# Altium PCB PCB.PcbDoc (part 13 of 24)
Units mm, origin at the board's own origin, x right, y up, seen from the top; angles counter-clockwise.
Board outline 100 x 160 mm, 10 copper layers (TOP_L1, L2, L3, L4, L5, L6, L7, L8, L9, BOTTOM_L10), stack 1.946 mm thick; 1358 components, 1149 nets, 6777 pads, 10914 vias.
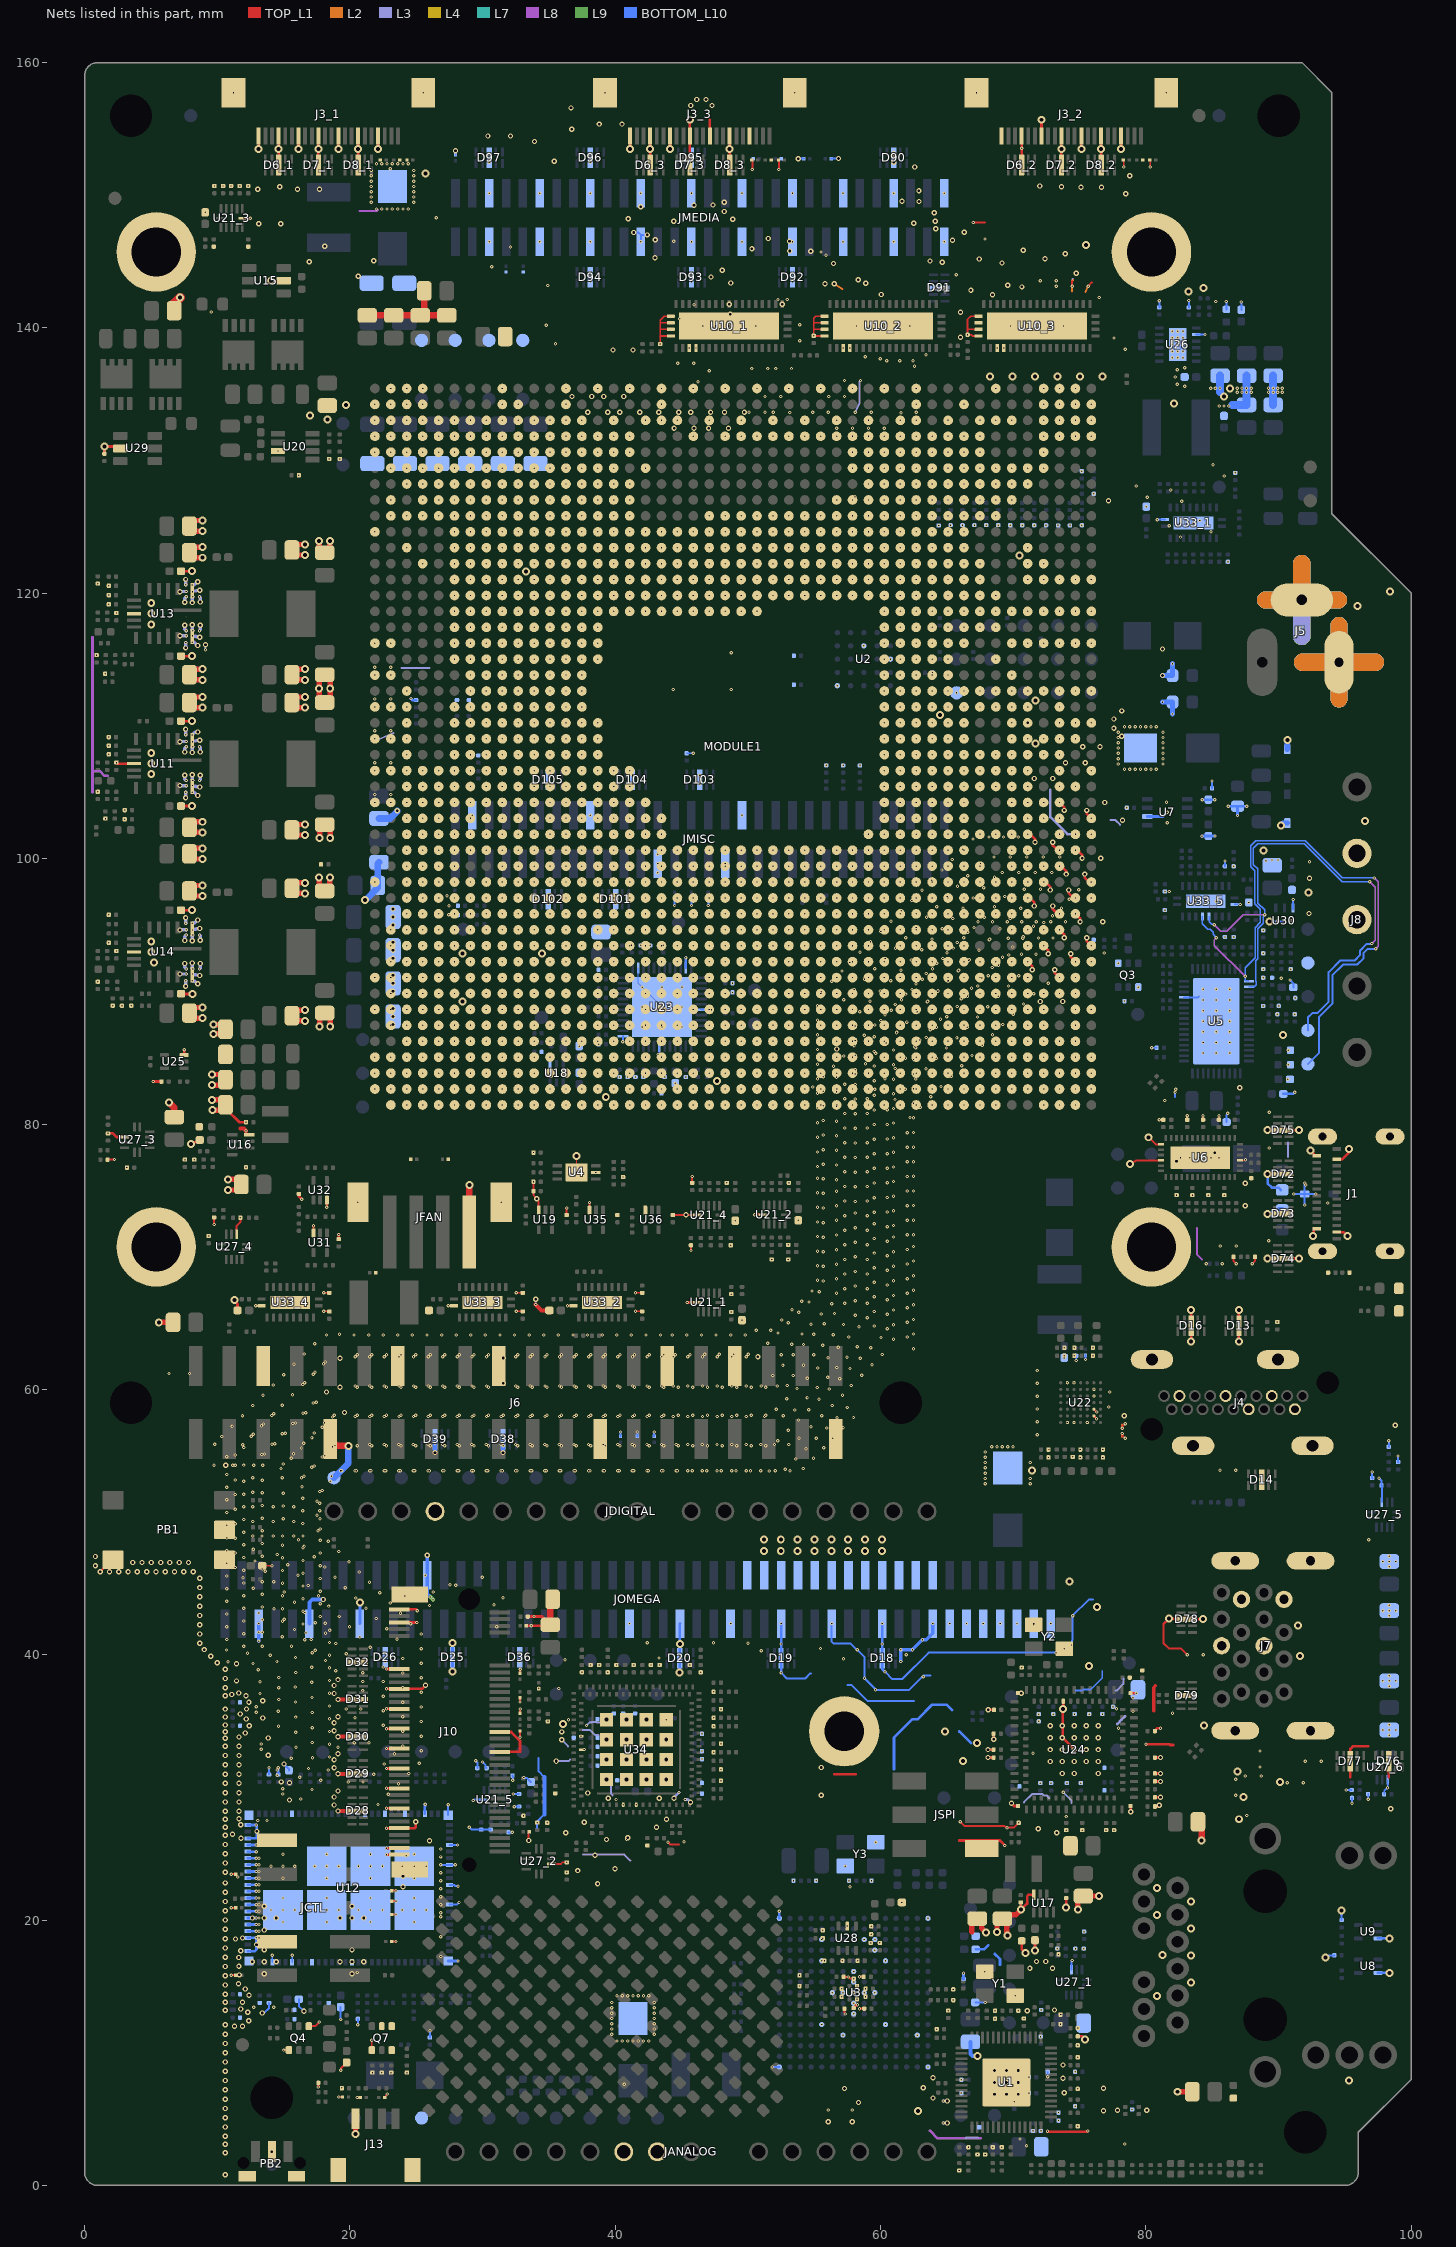
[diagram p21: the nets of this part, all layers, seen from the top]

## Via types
v1: diameter 0.25, hole 0.1, TOP_L1 to L2, tented both sides, 3439 vias
v2: diameter 0.25, hole 0.1, L2 to L3, tented both sides, 2256 vias
v3: diameter 0.25, hole 0.1, L9 to BOTTOM_L10, tented both sides, 1685 vias
v4: diameter 0.25, hole 0.1, L8 to L9, tented both sides, 1675 vias
v5: diameter 0.4, hole 0.2, L3 to L8, tented both sides, 1251 vias
v6: diameter 0.6, hole 0.3, TOP_L1 to BOTTOM_L10, tented both sides, 600 vias
v7: diameter 0.24, hole 0.1, TOP_L1 to L2, tented both sides, 8 vias

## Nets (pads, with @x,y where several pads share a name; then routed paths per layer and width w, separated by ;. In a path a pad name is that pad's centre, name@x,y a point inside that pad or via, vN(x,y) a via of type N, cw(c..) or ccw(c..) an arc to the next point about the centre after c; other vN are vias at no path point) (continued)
GND: (continued)
  other v2: 10.6,0.8 10.6,2.452 14.117,2.549 71,3 10.6,3.102 78.406,3.118 70.5,3.5 10.6,3.702 10.6,4.402 10.6,5.102 76.798,5.62 77.848,5.674 80.048,5.674 10.6,5.802 10.6,6.502 68.581,6.859 69.481,6.859 70.381,6.859 73.848,6.974 10.6,7.202 76.798,7.32 68.581,7.759 69.481,7.759 70.381,7.759 10.6,7.902 73.748,8.074 10.6,8.602 68.581,8.659 69.481,8.659 70.381,8.659 73.748,9.074 10.6,9.302 10.6,10.002 10.6,10.702 10.6,11.402 11.3,12 11.9,12 10.6,12.102 12.367,12.413 12.293,13.052 71.048,13.174 10.6,13.2 73.1,13.225 11.762,13.3 10.6,13.8 11.901,13.801 12.397,14.327 10.6,14.4 12.1,14.8 10.6,15.1 11.6,15.2 10.6,15.8 11.657,15.866 71.25,16.375 72.95,16.375 10.6,16.5 11.632,16.525 71.75,16.875 72.45,16.875 11.628,17.175 10.6,17.2 11.776,17.689 10.6,17.9 11.373,18.578 10.6,18.6 11.902,18.65 10.6,19.3 10.6,20 10.6,20.7 10.6,21.4 10.6,22.1 38.665,22.744 10.6,22.8 10.6,23.601 37.179,23.729 39.975,23.875 10.6,24.301 38.465,24.889 10.6,25.001 69.36,25.622 10.6,25.701 45.173,25.913 26,25.98 39.341,26.074 11.789,26.167 40.94,26.203 10.6,26.401 11.144,26.459 36.275,26.575 73.269,26.575 71.875,26.875 10.6,27.001 43.103,26.997 11.777,27.176 37.67,27.373 24.961,27.403 10.6,27.6 43.856,27.609 11.64,27.634 73.991,27.799 87.6,27.875 78.841,28.174 10.6,28.201 11.64,28.201 81.009,28.643 18.806,28.675 10.6,28.901 11.64,28.901 15.443,29.052 40.06,29.081 16.287,29.12 39.46,29.181 43.302,29.175 81.091,29.249 18.806,29.275 55.52,29.403 86.766,29.408 14.943,29.502 37.924,29.573 10.6,29.601 11.64,29.601 73.766,29.639 19.106,29.725 17.141,29.844 14.943,29.902 10.6,30.301 11.64,30.301 15.443,30.352 90.64,30.349 91.84,30.349 14.825,30.413 17.788,30.527 86.766,30.608 16.223,30.762 87.482,30.86 88.682,30.86 14.525,30.913 10.6,31.001 11.64,31.001 19.106,31.025 73.691,31.049 74.591,31.049 76.391,31.049 14.525,31.313 18.377,31.316 16.876,31.422 18.806,31.475 55.52,31.503 88.597,31.542 10.6,31.701 11.64,31.701 15.025,31.763 72.791,31.949 73.691,31.949 74.591,31.949 75.491,31.949 76.391,31.949 92,31.975 93.2,31.975 18.806,32.075 15.586,32.184 17.176,32.246 68.091,32.249 81.091,32.249 18.462,32.294 10.6,32.401 11.64,32.401 13.849,32.425 19.106,32.525 88.597,32.742 68.091,32.849 72.791,32.849 73.691,32.849 74.591,32.849 75.491,32.849 76.391,32.849 13.327,32.875 15.931,33.026 10.6,33.101 11.64,33.101 18.462,33.251 13.327,33.275 17.164,33.382 68.516,33.624 10.6,33.701 13.849,33.725 72.791,33.749 73.691,33.749 74.591,33.749 75.491,33.749 76.391,33.749 11.64,33.801 19.106,33.825 12.1,34.101 15.918,34.162 10.6,34.201 18.462,34.207 18.806,34.275 77.921,34.449 81.09,34.453 17.168,34.507 14.609,34.612 12.417,34.651 72.791,34.649 73.691,34.649 74.591,34.649 75.491,34.649 76.391,34.649 37.832,34.67 10.6,34.701 18.806,34.875 36.471,35.099 12.185,35.149 18.46,35.183 13.427,35.225 10.6,35.301 15.906,35.298 19.106,35.325 11.733,35.535 81.994,35.58 17.156,35.643 12.927,35.675 14.597,35.748 79.021,35.749 68.116,35.849 10.6,35.901 12.202,35.909 77.778,35.926 12.927,36.075 18.46,36.139 12.386,36.422 15.893,36.435 13.427,36.525 14.64,36.625 19.106,36.625 79.021,36.749 17.143,36.779 10.6,36.901 12.165,36.901 11.097,37.004 13.226,37.075 18.46,37.096 18.806,37.075 70.605,37.085 11.613,37.11 10.6,37.501 14.64,37.505 15.881,37.571 18.806,37.675 25.7,37.7 17.131,37.915 13.226,37.955 11.45,38.024 18.46,38.052 19.106,38.125 10.6,38.201 14.64,38.287 15.915,38.655 13.099,38.871 10.6,38.901 18.46,39.008 17.118,39.051 11.45,39.324 12.7,39.341 10.005,39.396 10.806,39.459 14.496,39.495 15.903,39.791 9.51,39.891 13.991,39.949 18.46,39.965 84.304,40.004 12.282,40.102 17.153,40.136 10.691,40.349 9.015,40.386 12.003,40.629 13.391,40.649 15.591,40.649 8.674,40.859 18.46,40.921 10.719,41.151 17.091,41.149 14.891,41.349 8.674,41.559 12.003,41.585 16.691,41.649 13.397,41.681 18.475,41.838 10.719,42.108 8.674,42.259 16.469,42.313 18.131,42.379 14.923,42.519 12.003,42.542 13.397,42.637 17.76,42.878 8.674,42.959 10.719,43.064 16.469,43.27 14.923,43.476 12.003,43.498 13.397,43.594 8.674,43.659 17.76,43.834 10.719,44.021 16.469,44.226 8.674,44.359 14.923,44.432 12.003,44.454 13.397,44.55 17.76,44.79 10.719,44.977 8.674,45.059 16.469,45.182 14.923,45.388 12.003,45.411 13.397,45.507 17.76,45.747 8.674,45.759 10.719,45.933 16.469,46.139 1.179,46.254 1.879,46.254 2.579,46.254 3.279,46.254 3.979,46.254 4.679,46.254 5.379,46.254 6.079,46.254 6.779,46.254 7.479,46.254 8.179,46.254 12.003,46.367 14.923,46.345 13.397,46.463 0.817,46.7 17.76,46.703 10.719,46.89 3.629,46.954 4.329,46.954 5.029,46.954 5.729,46.954 6.429,46.954 7.129,46.954 7.829,46.954 16.469,47.095 14.923,47.301 12.003,47.324 0.817,47.4 13.397,47.419 17.76,47.66 10.719,47.846 16.469,48.052 14.923,48.258 12.003,48.28 13.397,48.376 17.76,48.616 10.719,48.803 13.377,48.946 14.923,48.946 16.466,48.946 12.003,49.236 13.397,49.332 17.76,49.478 10.719,49.759 16.446,49.889 12.003,50.193 14.966,50.246 17.745,50.257 13.397,50.289 10.719,50.716 16.446,50.845 17.733,50.851 12.003,51.149 14.966,51.202 13.397,51.245 17.732,51.426 10.719,51.672 16.446,51.802 12.003,52.106 14.966,52.159 13.397,52.201 17.728,52.302 10.719,52.628 16.391,52.649 12.003,53.062 18.505,53.08 13.397,53.158 14.891,53.349 16.351,53.348 10.719,53.585 19.283,53.858 20.383,53.858 21.483,53.858 22.583,53.858 23.683,53.858 24.783,53.858 25.883,53.858 26.983,53.858 28.083,53.858 29.183,53.858 30.283,53.858 31.383,53.858 32.483,53.858 33.583,53.858 34.683,53.858 35.783,53.858 36.883,53.858 37.983,53.858 39.083,53.858 40.183,53.858 41.283,53.858 42.383,53.858 43.483,53.858 44.583,53.858 45.459,53.858 46.559,53.858 47.666,53.858 48.766,53.858 49.866,53.858 50.966,53.858 52.05,53.858 53.162,53.858 85.575,53.9 86.775,53.9 54.159,54.035 17.129,54.126 10.65,54.269 12.003,54.292 13.44,54.269 14.974,54.371 54.937,54.813 10.719,54.91 17.906,54.904 13.346,55.089 15.752,55.149 55.715,55.591 12.003,55.622 18.684,55.682 9.819,55.867 14.124,55.867 21.483,55.849 22.583,55.849 23.683,55.849 24.783,55.849 25.883,55.849 26.983,55.849 28.083,55.849 29.183,55.849 30.283,55.849 31.383,55.849 32.483,55.849 33.583,55.849 34.683,55.849 35.783,55.849 36.883,55.849 37.983,55.849 39.083,55.849 40.183,55.849 41.283,55.849 42.383,55.849 43.483,55.849 44.583,55.849 45.459,55.849 46.559,55.849 47.666,55.849 48.766,55.849 49.866,55.849 50.966,55.849 51.998,55.849 53.072,55.849 16.53,55.927 53.852,56.32 56.392,56.32 78.424,56.319 10.34,56.445 12.559,56.474 71.8,56.586 14.901,56.645 17.308,56.705 57.169,57.098 54.75,57.175 11.118,57.223 13.337,57.251 78.424,57.409 15.679,57.422 18.085,57.482 71.8,57.552 57.947,57.876 51.25,57.95 20.397,57.958 21.497,57.958 22.597,57.958 23.697,57.958 24.797,57.958 25.897,57.958 26.997,57.958 28.097,57.958 29.197,57.958 30.297,57.958 31.397,57.958 32.497,57.958 33.597,57.958 34.697,57.958 35.797,57.958 36.897,57.958 37.997,57.958 39.097,57.958 40.197,57.958 41.297,57.958 42.397,57.958 43.497,57.958 44.372,57.958 45.472,57.958 46.579,57.958 47.679,57.958 48.779,57.958 49.879,57.958 11.896,58 52.657,58.01 55.563,58.01 78.357,58.019 14.115,58.029 18.809,58.048 16.457,58.2 19.596,58.25 53.52,58.45 71.8,58.517 77.199,58.671 12.673,58.778 56.341,58.788 14.893,58.807 17.235,58.978 54.456,59.365 71.8,59.483 13.451,59.556 57.119,59.566 15.671,59.585 18.23,59.796 77.275,59.8 19.25,60.15 55.234,60.143 20.397,60.258 21.497,60.258 22.597,60.258 23.697,60.258 24.797,60.258 25.897,60.258 26.997,60.258 28.097,60.258 29.197,60.258 30.297,60.258 32.497,60.258 33.597,60.258 34.697,60.258 35.797,60.258 36.897,60.258 37.997,60.258 39.097,60.258 40.197,60.258 41.297,60.258 42.397,60.258 43.497,60.258 44.372,60.258 45.472,60.258 46.579,60.258 47.679,60.258 48.779,60.258 49.879,60.258 51.012,60.258 52.197,60.258 52.949,60.296 57.796,60.296 14.229,60.334 16.449,60.363 71.8,60.449 56.012,60.921 53.406,61.047 58.574,61.074 15.007,61.112 17.226,61.141 71.8,61.414 56.688,61.65 54.184,61.825 59.351,61.851 15.785,61.89 18.004,61.918 19.25,62.35 31.557,62.365 57.466,62.428 20.397,62.458 21.497,62.458 22.597,62.458 23.697,62.458 24.797,62.458 25.897,62.458 26.997,62.458 28.097,62.458 29.197,62.458 30.297,62.458 32.497,62.458 33.597,62.458 34.697,62.458 35.797,62.458 36.897,62.458 37.997,62.458 39.097,62.458 40.197,62.458 41.297,62.458 42.397,62.458 43.497,62.458 44.372,62.458 45.472,62.458 46.579,62.458 47.679,62.458 48.779,62.458 49.879,62.458 50.75,62.45 52.518,62.618 54.962,62.603 60.129,62.629 16.563,62.667 62.476,63.069 58.244,63.206 55.638,63.333 53.296,63.396 17.34,63.445 60.972,63.78 18.233,64.101 20.308,64.099 21.408,64.099 22.508,64.099 23.608,64.099 24.708,64.099 25.808,64.099 26.908,64.099 28.008,64.099 29.108,64.099 30.208,64.099 31.308,64.099 32.408,64.099 33.508,64.099 34.608,64.099 35.708,64.099 36.808,64.099 37.908,64.099 39.008,64.099 40.108,64.099 41.208,64.099 42.308,64.099 43.408,64.099 44.284,64.099 45.384,64.099 46.491,64.099 47.591,64.099 48.691,64.099 49.791,64.099 56.416,64.111 19.22,64.143 62.476,64.169 54.073,64.174 50.614,64.459 51.714,64.459 59.514,64.771 60.972,64.88 54.75,64.904 57.194,64.889 52.546,65.226 62.476,65.269 58.076,65.589 55.528,65.682 59.514,65.871 60.972,65.98 53.324,66.004 62.476,66.369 34.007,66.4 56.306,66.459 54.047,66.632 58.076,66.689 59.514,66.971 60.972,67.08 56.679,67.234 54.825,67.41 62.476,67.469 58.076,67.789 59.514,68.071 60.972,68.18 55.236,68.218 56.679,68.334 62.476,68.569 58.076,68.889 59.514,69.171 60.972,69.28 55.236,69.318 56.679,69.434 84.552,69.463 85.752,69.463 88.005,69.463 62.476,69.669 58.076,69.989 59.514,70.271 60.972,70.38 55.236,70.418 56.679,70.534 62.476,70.769 85.604,70.799 86.805,70.799 58.076,71.089 89.255,71.199 59.514,71.371 60.972,71.48 55.236,71.518 56.679,71.634 62.476,71.644 58.076,72.189 60.972,72.355 59.514,72.471 55.236,72.618 56.679,72.734 62.476,72.744 58.076,73.289 59.514,73.346 60.972,73.455 55.236,73.718 56.679,73.834 87.482,73.836 62.476,73.852 93.705,74.045 58.076,74.165 59.514,74.446 60.972,74.563 55.236,74.818 56.679,74.934 62.476,74.952 58.076,75.265 92.04,75.405 87.482,75.536 59.514,75.553 60.972,75.663 56.679,75.809 55.236,75.918 62.476,76.052 58.076,76.372 59.514,76.653 60.972,76.763 55.236,76.794 56.679,76.909 62.476,77.152 58.076,77.472 82.6,77.465 83.3,77.465 84.1,77.465 84.9,77.465 85.5,77.465 59.514,77.753 60.972,77.863 55.236,77.894 56.679,78.017 89.283,78.186 62.476,78.259 58.076,78.572 59.514,78.853 60.972,78.97 55.236,79.001 56.679,79.117 62.476,79.359 58.076,79.672 59.514,79.961 60.972,80.07 55.236,80.101 56.679,80.217 62.476,80.459 58.076,80.78 89.283,80.88 59.514,81.061 60.972,81.17 55.236,81.201 56.679,81.324 62.476,81.559 81.402,81.767 58.076,81.88 59.514,82.161 60.972,82.27 55.236,82.309 56.679,82.424 82.25,82.615 62.476,82.667 58.076,82.98 59.514,83.261 60.972,83.378 55.236,83.409 56.679,83.524 62.476,83.767 58.076,84.08 59.514,84.368 60.972,84.478 55.236,84.509 62.476,84.867 58.076,85.187 59.514,85.468 60.972,85.578 55.236,85.616 56.682,85.65 62.569,85.822 58.076,86.287 62.955,86.335 59.514,86.568 55.236,86.716 61.211,86.917 63.733,87.113 58.076,87.387 61.989,87.694 55.236,87.816 60.019,87.803 64.51,87.891 58.418,88.472 62.767,88.472 60.797,88.581 65.294,88.674 55.236,88.924 72.032,89.236 73.732,89.236 59.196,89.25 63.55,89.255 57.226,89.359 61.575,89.359 66.071,89.452 29.082,89.836 32.682,89.836 55.533,89.972 59.973,90.028 64.328,90.033 58.004,90.137 62.358,90.142 66.849,90.23 56.311,90.75 7.614,90.797 8.127,90.805 60.751,90.806 65.105,90.811 58.782,90.914 63.136,90.92 67.627,91.008 8.129,91.308 57.088,91.528 61.534,91.589 65.883,91.589 7.662,91.685 8.162,91.685 59.565,91.697 63.914,91.697 68.41,91.791 57.669,92.168 29.082,92.236 32.682,92.236 62.312,92.367 66.666,92.372 60.343,92.475 64.692,92.475 69.188,92.568 58.446,92.946 63.09,93.144 61.121,93.253 65.475,93.258 69.966,93.346 59.23,93.729 63.873,93.928 68.222,93.928 61.898,94.031 66.252,94.036 70.744,94.124 7.662,94.246 8.662,94.246 60.007,94.507 8.129,94.623 7.651,94.632 64.651,94.705 69,94.705 62.681,94.814 67.03,94.814 71.521,94.902 8.127,95.126 72.292,95.181 60.785,95.285 65.429,95.483 69.778,95.483 63.459,95.592 67.808,95.592 72.959,95.703 92.289,95.868 61.563,96.062 66.207,96.261 70.555,96.261 73.635,96.259 64.237,96.37 68.586,96.37 71.582,96.436 62.341,96.84 74.205,96.94 66.984,97.039 65.015,97.147 69.364,97.147 63.119,97.618 72.782,97.636 74.182,97.636 74.93,97.646 70.813,97.696 72.054,97.696 67.762,97.817 65.793,97.925 63.84,98.37 92.328,98.528 68.586,98.594 66.571,98.703 75.382,98.836 69.176,98.95 70.417,98.95 71.657,98.95 72.897,98.95 64.618,99.148 67.528,99.628 92.321,99.769 65.401,99.931 75.182,100.036 76.582,100.036 68.537,100.123 69.778,100.123 71.018,100.123 72.258,100.123 73.498,100.123 66.178,100.709 71.632,101.236 72.982,101.236 66.956,101.487 68.163,101.628 69.263,101.628 70.363,101.628 78.226,102.892 23.573,103.603 73.832,103.636 75.532,103.636 76.882,104.235 21.882,104.836 23.082,104.836 7.662,105.885 8.662,105.885 71.582,106.036 72.982,106.036 21.882,107.236 23.082,107.236 73.932,107.236 75.432,107.236 7.662,108.445 8.662,108.445 75.232,108.436 76.532,108.436 7.651,108.831 78.182,109.235 8.127,109.325 21.882,109.636 23.082,109.636 78.182,111.135 21.882,112.036 23.082,112.036 21.882,114.436 23.082,114.436 7.614,116.296 8.127,116.305 7.651,116.799 7.662,117.185 8.662,117.185 8.662,119.745 8.129,120.123 8.127,120.625 82.602,124.236 84.902,124.636 81.754,125.085 84.054,125.485 82.702,126.936 77.169,126.978 80.102,127.236 81.854,127.785 79.254,128.085 85.902,128.836 85.054,129.685 27.882,130.636 30.282,130.636 32.682,130.636 44.432,132.436 45.932,132.436 47.032,132.436 48.532,132.436 56.682,132.436 57.882,132.436 59.082,132.436 60.282,132.436 37.932,133.636 39.432,133.636 40.332,133.636 41.832,133.636 43.282,133.636 44.782,133.636 45.682,133.636 47.182,133.636 48.232,133.636 49.732,133.636 50.082,133.636 51.282,133.636 53.156,133.627 54.882,133.636 56.059,133.636 58.082,133.636 59.282,133.636 61.531,133.619 51.91,133.642 62.681,133.654 36.732,134.836 38.232,134.836 39.132,134.836 40.632,134.836 51.282,134.836 52.482,134.836 56.082,134.836 57.282,134.836 46.232,135.936 57.282,136.036 47.081,136.785 50.282,136.936 51.482,136.936 52.082,136.936 53.282,136.936 62.556,137.113 44.708,137.328 45.906,137.33 60.449,137.523 61.432,137.536 62.432,137.536 59.982,137.686 58.832,137.836 63.422,137.979 39.832,138.336 41.332,138.336 78.442,138.392 53.904,139.041 77.593,139.241 66.021,139.291 53.904,140.24 9.553,141.203 66.021,141.191 76.485,142.3 68.43,142.504 60.05,142.515 64.845,142.712 66.804,142.84 70.648,143.092 73.236,143.149 69.572,143.21 55.804,143.34 56.504,143.34 58.873,143.359 48.703,143.383 72.036,143.549 73.236,143.549 58.304,143.64 47.21,143.844 20.625,143.891 65.7,144 74.74,144.117 48.061,144.35 56.446,144.859 69.143,144.897 64.648,144.95 16.925,144.991 63.716,145.04 21.794,145.06 67.443,145.197 72.393,145.206 42.995,145.282 55.887,145.469 73.908,145.58 55.505,145.726 54.741,145.783 53.158,145.797 70.747,145.858 50.297,145.969 18.094,146.16 44.394,146.526 53.13,146.526 65.413,146.608 43.023,146.643 67.861,146.701 51.538,146.738 66.312,147.201 64.143,147.482 13.126,147.852 14.779,147.852 62.506,147.89 66.972,147.95 44.398,148.032 64.121,148.036 48.855,148.201 40.985,148.228 64.035,148.679 48.215,148.775 41.926,149.131 45.938,149.258 47.363,149.261 48.215,149.471 62.889,149.526 61.611,149.544 78.463,150.113 62.884,150.343 13.048,150.45 16.048,150.45 17.701,150.45 75.1,150.6 76.649,150.6 14.701,150.65 73.628,150.651 72,150.7 78.768,151.474 23.031,151.987 62.567,152.133 60.979,152.493 35.395,152.57 53.782,152.752 56.825,152.765 60.979,153.14 27.959,153.366 70.624,153.539 30.4,154.465 32.1,154.465 36.728,154.977 38.8,155.365 40.5,155.365 36.659,156.584 45.689,156.765 47.289,156.765 46.139,157.215 46.839,157.215
  other v3: 10.6,0.8 10.6,2.452 10.6,3.102 10.6,3.702 71.481,4.114 72.081,4.114 10.6,4.402 56.062,4.79 57.862,4.79 73.406,4.892 10.6,5.102 73.406,5.492 76.798,5.62 77.848,5.674 80.048,5.674 78.948,5.724 10.6,5.802 74.656,5.97 70.081,6.309 10.6,6.502 68.581,6.859 69.481,6.859 70.381,6.859 66.081,6.963 71.181,6.959 73.848,6.974 10.6,7.202 76.798,7.32 68.581,7.759 69.481,7.759 70.381,7.759 10.6,7.902 66.081,7.959 73.748,8.074 71.181,8.159 74.656,8.559 10.6,8.602 68.581,8.659 69.481,8.659 70.381,8.659 63.563,8.929 73.748,9.074 10.6,9.302 10.6,10.002 10.6,10.702 40.132,10.886 40.532,10.886 40.932,10.886 41.332,10.886 41.732,10.886 42.132,10.886 42.532,10.886 72.054,11.213 57.163,11.329 62.763,11.329 39.732,11.386 42.932,11.386 10.6,11.402 39.732,11.786 42.932,11.786 11.3,12 11.9,12 10.6,12.102 55.563,12.129 60.363,12.129 39.732,12.186 42.932,12.186 12.367,12.413 39.732,12.586 42.932,12.586 57.963,12.929 39.732,12.986 42.932,12.986 13.4,13 12.293,13.052 16.54,13.119 10.6,13.2 72.1,13.225 11.762,13.3 39.732,13.386 42.932,13.386 57.963,13.729 10.6,13.8 11.901,13.801 39.732,13.786 42.932,13.786 40.132,14.286 40.532,14.286 40.932,14.286 41.332,14.286 41.732,14.286 42.132,14.286 42.532,14.286 12.397,14.327 10.6,14.4 56.363,14.529 57.163,14.529 57.963,14.529 58.763,14.529 59.563,14.529 12.1,14.8 10.6,15.1 11.6,15.2 57.963,15.329 10.6,15.8 11.657,15.866 57.963,16.129 71.25,16.375 72.95,16.375 10.6,16.5 11.632,16.525 71.75,16.875 72.45,16.875 55.563,16.929 60.363,16.929 11.628,17.175 10.6,17.2 11.776,17.689 59.563,17.729 73.321,17.843 74.681,17.843 75.316,17.843 10.6,17.9 55.563,18.529 58.768,18.534 59.568,18.534 11.373,18.578 10.6,18.6 11.902,18.65 75.328,19.127 10.6,19.3 14.95,19.86 18.25,19.86 21.55,19.86 24.85,19.86 10.6,20 63.563,20.129 26.847,20.25 26.849,20.56 10.6,20.7 14.05,20.76 14.95,20.76 15.85,20.76 17.35,20.76 18.25,20.76 19.15,20.76 20.65,20.76 21.55,20.76 22.45,20.76 23.95,20.76 24.85,20.76 25.75,20.76 26.849,21.16 10.6,21.4 14.95,21.66 18.25,21.66 21.55,21.66 24.85,21.66 26.849,21.76 10.6,22.1 26.849,22.36 57.693,22.516 38.665,22.744 10.6,22.8 26.849,22.96 53.438,22.975 55.138,22.975 57.613,22.974 59.313,22.974 14.95,23.16 18.25,23.16 21.55,23.16 24.85,23.16 26.849,23.56 10.6,23.601 37.179,23.729 39.975,23.875 14.05,24.06 14.95,24.06 15.85,24.06 17.35,24.06 18.25,24.06 19.15,24.06 20.65,24.06 21.55,24.06 22.45,24.06 23.95,24.06 24.85,24.06 25.75,24.06 10.6,24.301 26.849,24.76 38.465,24.889 14.95,24.96 18.25,24.96 21.55,24.96 24.85,24.96 10.6,25.001 26.849,25.36 10.6,25.701 39.341,26.074 40.841,26.074 11.789,26.167 10.6,26.401 11.144,26.459 73.269,26.551 36.275,26.575 71.875,26.875 10.6,27.001 43.103,26.997 11.777,27.176 37.67,27.373 10.6,27.6 43.856,27.609 11.64,27.634 78.841,28.174 10.6,28.201 11.64,28.201 98.45,28.397 81.009,28.643 69.862,28.795 10.6,28.901 11.64,28.901 39.46,29.181 43.302,29.175 81.091,29.249 37.924,29.573 10.6,29.601 11.64,29.601 10.6,30.301 11.64,30.301 72.041,30.324 72.841,30.324 74.041,30.324 75.091,30.324 81.091,30.449 10.6,31.001 11.64,31.001 73.691,31.049 74.591,31.049 76.391,31.049 81.091,31.049 10.6,31.701 11.64,31.701 35.56,31.881 72.791,31.949 73.691,31.949 74.591,31.949 75.491,31.949 76.391,31.949 46.535,32.137 68.091,32.249 81.091,32.249 10.6,32.401 11.64,32.401 13.827,32.425 19.106,32.525 71.48,32.582 46.535,32.737 68.091,32.849 72.791,32.849 73.691,32.849 75.491,32.849 76.391,32.849 19.106,33.025 10.6,33.101 11.64,33.101 35.96,33.581 68.516,33.624 10.6,33.701 13.827,33.725 72.791,33.749 73.691,33.749 74.591,33.749 75.491,33.749 76.391,33.749 11.64,33.801 98.336,33.925 46.535,34.037 12.1,34.101 10.6,34.201 35.96,34.181 97.836,34.325 98.336,34.325 98.836,34.325 12.417,34.651 72.791,34.649 73.691,34.649 74.591,34.649 75.491,34.649 76.391,34.649 10.6,34.701 98.336,34.725 71.916,34.974 12.185,35.149 10.6,35.301 11.733,35.535 71.916,35.524 73.016,35.524 74.616,35.524 75.716,35.524 76.716,35.524 68.116,35.849 10.6,35.901 12.202,35.909 77.516,36.074 12.386,36.422 10.6,36.901 12.165,36.901 11.097,37.004 70.605,37.085 11.613,37.11 59.615,37.367 98.336,37.625 97.836,38.025 98.336,38.025 98.836,38.025 19.106,38.125 10.6,38.201 63.221,38.344 98.336,38.425 10.6,38.901 10.005,39.396 22.651,39.488 32.806,39.489 57.2,39.7 43.3,39.75 9.51,39.891 22.651,40.135 32.806,40.135 73.217,40.148 51,40.3 9.015,40.386 58.225,40.375 61.526,40.375 55.461,40.471 74.384,40.727 8.674,40.859 50,40.868 42.4,40.9 47.4,40.9 63.148,41.124 8.674,41.559 8.674,42.259 65.196,42.35 66.466,42.35 67.736,42.35 69.006,42.35 70.276,42.35 71.546,42.35 72.816,42.35 41.071,42.355 48.691,42.355 74.477,42.931 98.336,42.925 8.674,42.959 13.132,43.141 97.836,43.325 98.336,43.325 98.836,43.325 8.674,43.659 98.336,43.725 8.674,44.359 8.674,45.059 8.674,45.759 1.179,46.254 1.879,46.254 2.579,46.254 3.279,46.254 3.979,46.254 4.679,46.254 5.379,46.254 6.079,46.254 6.779,46.254 7.479,46.254 8.179,46.254 98.336,46.625 0.817,46.7 3.629,46.954 4.329,46.954 5.029,46.954 5.729,46.954 6.429,46.954 7.129,46.954 7.829,46.954 97.836,47.025 98.336,47.025 98.836,47.025 0.817,47.4 98.336,47.425 25.826,47.498 12.677,48.946 14.223,48.946 15.766,48.946 67.876,52.882 71.276,52.882 67.876,53.282 71.276,53.282 67.876,53.682 67.876,54.082 11.16,54.269 12.74,54.269 67.876,54.482 71.276,54.482 67.876,54.882 26.416,55.234 31.541,55.234 67.876,55.282 68.376,55.682 68.776,55.682 69.176,55.682 69.576,55.682 69.976,55.682 21.65,55.75 26.416,56.561 31.541,56.561 98.79,57.3 20.55,58.05 21.65,58.05 22.75,58.05 23.85,58.05 24.95,58.05 26.05,58.05 19.596,58.25 18.23,59.796 20.55,60.15 21.65,60.15 22.75,60.15 23.85,60.15 24.95,60.15 26.05,60.15 31.557,60.467 31.557,62.365 73.837,62.369 45.325,73.165 87.482,73.836 87.482,75.536 44.523,83.081 90.673,83.367 40.323,83.541 40.923,83.541 41.523,83.541 42.123,83.541 43.723,83.541 45.323,83.541 90.713,84.467 43.223,85.237 84.303,85.347 85.303,85.347 86.303,85.347 90.713,85.567 37.275,85.866 38.748,86.016 84.303,86.147 85.303,86.147 86.303,86.147 84.303,86.947 85.303,86.947 86.303,86.947 42.023,87.316 43.523,87.316 45.023,87.316 23.25,87.5 84.303,87.747 85.303,87.747 86.303,87.747 23.25,88.1 89.903,88.272 91.213,88.272 84.303,88.547 85.303,88.547 86.303,88.547 23.25,88.7 42.023,88.816 45.023,88.816 88.828,88.9 90.003,88.897 72.032,89.236 73.732,89.236 78.382,89.265 84.303,89.347 85.303,89.347 86.303,89.347 91.253,89.497 48.838,89.916 23.25,90 84.303,90.147 85.303,90.147 86.303,90.147 43.523,90.316 45.023,90.316 79.407,90.316 23.25,90.6 48.838,90.616 90.188,90.997 88.828,91.022 23.25,91.2 73.132,91.636 88.828,91.672 90.903,91.672 77.907,92.115 23.25,92.5 74.332,92.836 88.828,92.867 76.857,92.883 23.25,93.1 41.223,93.466 41.923,93.466 42.623,93.466 43.623,93.466 23.25,93.7 73.832,94.036 85.953,94.097 86.603,94.097 88.828,94.597 23.25,95 75.032,95.236 76.732,95.236 89.933,95.318 90.433,95.318 90.933,95.318 23.25,95.6 27.452,95.782 92.289,95.868 81.426,96.12 23.25,96.2 27.461,96.451 71.582,96.436 72.982,96.436 34.944,96.63 40.024,96.63 87.753,96.699 83.703,96.795 84.503,96.795 85.303,96.795 27.31,97.202 34.944,97.277 40.024,97.277 81.426,97.52 72.782,97.636 74.182,97.636 92.328,98.528 73.982,98.836 75.382,98.836 43.199,98.929 86.603,99.424 43.199,99.629 48.279,99.629 89.05,99.85 89.5,99.9 89.95,99.9 75.182,100.036 43.199,100.329 71.632,101.236 84.223,101.699 85.204,101.702 81.603,102.703 29.229,103.278 38.119,103.278 49.549,103.278 23.573,103.603 73.832,103.636 78.553,103.828 86.2,103.95 87.6,103.95 81.548,104.258 41.294,105.631 46.374,105.631 84.978,105.852 71.582,106.036 72.982,106.036 41.294,106.277 46.374,106.277 78.382,106.736 78.782,106.736 79.182,106.736 79.582,106.736 79.982,106.736 80.382,106.736 80.782,106.736 55.899,107.028 57.169,107.028 58.439,107.028 77.91,107.136 81.282,107.136 73.932,107.236 75.432,107.236 77.91,107.536 81.282,107.536 77.91,107.936 81.282,107.936 77.91,108.336 81.282,108.336 75.232,108.436 76.532,108.436 77.91,108.736 81.282,108.736 77.91,109.136 81.282,109.136 77.91,109.536 81.282,109.536 78.382,109.936 78.782,109.936 79.182,109.936 79.582,109.936 79.982,109.936 80.382,109.936 80.782,109.936 24.6,112.065 65.722,112.496 44.362,112.749 48.73,112.749 56.737,113.036 81.248,113.8 63.903,114.024 60.737,115.036 48.73,115.525 58.737,116.036 32.682,118.636 35.082,118.636 62.682,118.636 53.082,119.836 38.682,121.036 44.682,121.036 56.682,121.036 45.882,122.236 86.175,122.375 64.369,125.106 65.269,125.133 66.169,125.133 67.069,125.133 67.969,125.133 68.869,125.133 69.769,125.128 70.669,125.128 71.569,125.128 72.469,125.128 73.369,125.123 74.269,125.123 75.169,125.128 82.575,125.3 83.575,125.3 84.575,125.3 80.025,126.535 77.169,126.978 58.069,127.272 76.069,127.501 86.725,129.075 75.169,129.201 44.432,132.436 45.932,132.436 47.032,132.436 48.532,132.436 37.932,133.636 39.432,133.636 40.332,133.636 41.832,133.636 43.282,133.636 44.782,133.636 45.682,133.636 47.182,133.636 48.232,133.636 49.732,133.636 85.53,134.12 85.88,134.12 86.23,134.12 36.732,134.836 38.232,134.836 39.132,134.836 40.632,134.836 86.88,135.15 87.23,135.15 87.93,135.15 89.23,135.15 89.93,135.15 90.28,135.15 84.88,135.45 85.23,135.45 86.88,135.45 87.23,135.45 87.58,135.45 87.93,135.45 89.23,135.45 89.58,135.45 89.93,135.45 90.28,135.45 82.91,135.6 82.36,135.75 82.21,136.3 82.36,136.85 82.91,137 81.99,137.75 82.39,137.75 82.79,137.75 81.99,138.25 82.39,138.25 82.79,138.25 39.832,138.336 41.332,138.336 81.99,138.75 82.39,138.75 82.79,138.75 81.99,139.25 82.39,139.25 82.79,139.25 81.99,139.75 82.39,139.75 82.79,139.75 44.866,140.69 48.659,141.04 45.927,141.751 48.582,141.791 52.582,141.791 85.255,141.995 86.05,141.998 52.259,142.14 52.959,142.14 68.43,142.504 60.05,142.515 66.804,142.84 64.104,143.015 64.751,143.015 70.648,143.092 69.572,143.21 55.804,143.34 58.873,143.359 38.119,143.493 45.739,143.493 53.359,143.493 58.304,143.64 20.625,143.891 74.74,144.117 38.119,144.14 45.739,144.14 53.359,144.14 69.143,144.897 64.648,144.95 63.716,145.04 21.794,145.06 67.443,145.197 72.393,145.206 73.908,145.58 70.747,145.858 30.499,146.492 34.309,146.492 38.119,146.492 45.739,146.492 49.549,146.492 53.359,146.492 57.169,146.492 60.979,146.492 64.789,146.492 53.13,146.526 65.413,146.608 51.538,146.738 42.409,147.011 41.403,147.193 66.312,147.201 64.143,147.482 13.126,147.852 14.779,147.852 62.506,147.89 64.121,148.036 40.985,148.228 64.035,148.679 22,148.966 22.4,148.966 22.8,148.966 23.2,148.966 23.6,148.966 24,148.966 24.4,148.966 41.926,149.131 21.6,149.466 24.8,149.466 62.889,149.526 61.611,149.544 21.6,149.866 24.8,149.866 78.463,150.113 30.499,150.141 34.309,150.141 38.119,150.141 41.929,150.141 45.739,150.141 49.549,150.141 53.359,150.141 57.169,150.141 60.979,150.141 64.789,150.141 21.6,150.266 24.8,150.266 62.884,150.343 13.048,150.45 75.1,150.6 76.649,150.6 14.701,150.65 73.628,150.651 21.6,150.666 24.8,150.666 72,150.7 21.6,151.066 24.8,151.066 21.6,151.466 24.8,151.466 78.768,151.474 21.6,151.866 24.8,151.866 62.567,152.133 22,152.366 22.4,152.366 22.8,152.366 23.2,152.366 23.6,152.366 24,152.366 24.4,152.366 30.499,152.494 38.119,152.494 45.739,152.494 60.979,152.493 35.395,152.57 30.499,153.14 38.119,153.14 45.739,153.14 60.979,153.14 33.911,154.056 30.4,154.465 32.1,154.465 36.728,154.977 38.8,155.365 40.5,155.365 36.659,156.584 45.689,156.765 47.289,156.765 46.139,157.215 46.839,157.215
  other v4: 10.6,0.8 10.6,2.452 10.6,3.102 10.6,3.702 10.6,4.402 65.03,4.709 56.062,4.79 57.862,4.79 10.6,5.102 10.6,5.802 10.6,6.502 68.581,6.859 69.481,6.859 70.381,6.859 10.6,7.202 40.687,7.622 68.581,7.759 69.481,7.759 70.381,7.759 10.6,7.902 10.6,8.602 68.581,8.659 69.481,8.659 70.381,8.659 10.6,9.302 10.6,10.002 10.6,10.702 10.6,11.402 11.3,12 11.9,12 10.6,12.102 12.367,12.413 13.4,13 12.293,13.052 16.54,13.119 10.6,13.2 11.762,13.3 12.75,13.428 14.25,13.428 10.6,13.8 11.901,13.801 12.397,14.327 10.6,14.4 12.1,14.8 10.6,15.1 11.6,15.2 10.6,15.8 11.657,15.866 13.55,15.95 20.15,15.95 20.561,16.055 10.6,16.5 11.632,16.525 12.65,16.85 13.55,16.85 14.45,16.85 19.25,16.85 20.15,16.85 21.05,16.85 11.628,17.175 10.6,17.2 26.847,17.25 11.776,17.689 13.55,17.75 20.15,17.75 10.6,17.9 12.958,18.152 11.373,18.578 10.6,18.6 11.902,18.65 13.15,18.66 26.847,18.75 13.15,19.16 13.55,19.25 10.6,19.3 13.15,19.66 18.25,19.86 21.55,19.86 24.85,19.86 10.6,20 12.65,20.15 13.55,20.15 14.45,20.15 19.25,20.15 20.15,20.15 21.05,20.15 13.15,20.16 13.15,20.66 10.6,20.7 18.25,20.76 19.15,20.76 20.65,20.76 21.55,20.76 22.45,20.76 23.95,20.76 24.864,20.759 25.75,20.76 13.55,21.05 20.15,21.05 13.15,21.16 10.6,21.4 13.15,21.66 21.55,21.66 24.85,21.66 10.6,22.1 13.15,22.16 13.15,22.66 10.6,22.8 13.15,23.16 18.25,23.16 24.85,23.16 11.55,23.25 10.6,23.601 13.15,23.66 18.25,24.06 23.95,24.06 24.85,24.06 25.75,24.06 13.15,24.16 10.6,24.301 13.15,24.66 24.25,24.847 24.85,24.96 10.6,25.001 10.6,25.701 26,25.98 11.789,26.167 10.6,26.401 11.144,26.459 12.988,26.682 10.6,27.001 11.777,27.176 13.05,27.5 13.75,27.5 10.6,27.6 11.64,27.634 78.841,28.174 10.6,28.201 11.64,28.201 98.45,28.397 22.109,28.715 69.862,28.795 10.6,28.901 11.64,28.901 81.091,29.249 22.887,29.493 10.6,29.601 11.64,29.601 23.665,30.271 10.6,30.301 11.64,30.301 19.884,30.412 20.984,30.412 81.091,30.449 21.806,30.988 10.6,31.001 11.64,31.001 24.442,31.048 73.691,31.049 74.591,31.049 76.391,31.049 81.091,31.049 10.6,31.701 11.64,31.701 22.584,31.766 25.22,31.826 72.791,31.949 73.691,31.949 74.591,31.949 75.491,31.949 76.391,31.949 68.091,32.249 81.091,32.249 10.6,32.401 11.64,32.401 23.362,32.544 25.369,32.761 72.791,32.849 73.691,32.849 74.591,32.849 75.491,32.849 76.391,32.849 10.6,33.101 11.64,33.101 23.975,33.119 20.33,33.359 21.43,33.359 68.516,33.624 10.6,33.701 72.791,33.749 73.691,33.749 74.591,33.749 75.491,33.749 76.391,33.749 11.64,33.801 25.369,33.861 12.1,34.101 10.6,34.201 23.975,34.219 12.417,34.651 72.791,34.649 73.691,34.649 74.591,34.649 75.491,34.649 76.391,34.649 22.519,34.677 10.6,34.701 25.369,34.961 12.185,35.149 20.379,35.258 10.6,35.301 23.975,35.319 11.733,35.535 22.519,35.777 10.6,35.901 12.202,35.909 19.715,35.909 20.815,35.909 25.369,36.061 12.386,36.422 23.975,36.419 19.987,36.659 20.581,36.812 22.519,36.877 10.6,36.901 12.165,36.901 11.097,37.004 70.605,37.085 11.613,37.11 25.369,37.161 20.973,37.296 35.742,37.449 10.6,37.501 23.975,37.519 22.519,37.977 20.975,37.986 10.6,38.201 58.789,38.218 25.369,38.261 63.221,38.344 23.975,38.619 20.973,38.635 18.938,38.791 10.6,38.901 22.519,39.077 20.491,39.287 25.369,39.361 10.005,39.396 61.521,39.494 18.16,39.569 36.205,39.62 57.2,39.7 23.975,39.719 43.3,39.75 22.304,39.775 9.51,39.891 61.92,39.987 19.714,40.065 73.217,40.148 51,40.3 17.382,40.347 9.015,40.386 58.225,40.375 62.399,40.375 25.369,40.461 55.461,40.471 21.526,40.553 18.936,40.842 8.674,40.859 50,40.868 42.4,40.9 47.4,40.9 16.604,41.125 23.545,41.168 20.748,41.331 8.674,41.559 25.369,41.561 18.158,41.62 15.827,41.902 22.767,41.946 19.97,42.109 31.075,42.116 8.674,42.259 24.591,42.339 17.38,42.398 15.049,42.68 21.989,42.724 19.193,42.887 8.674,42.959 23.814,43.116 16.602,43.176 14.271,43.458 21.211,43.501 8.674,43.659 18.415,43.664 25.99,43.709 30.862,43.766 23.036,43.894 15.824,43.954 17.978,44.16 20.433,44.279 31.538,44.287 8.674,44.359 24.132,44.426 17.637,44.442 22.258,44.672 15.047,44.731 26.288,44.731 12.715,45.014 8.674,45.059 19.656,45.057 16.859,45.22 27.964,45.228 27.546,45.264 21.48,45.45 14.269,45.509 8.674,45.759 11.938,45.791 18.878,45.835 29.982,45.843 25.687,45.982 16.081,45.998 20.702,46.228 1.179,46.254 1.879,46.254 2.579,46.254 3.279,46.254 3.979,46.254 4.679,46.254 5.379,46.254 6.079,46.254 6.779,46.254 7.479,46.254 8.179,46.254 13.627,46.279 11.36,46.569 18.1,46.613 0.817,46.7 15.303,46.776 3.629,46.954 4.329,46.954 5.029,46.954 5.729,46.954 6.429,46.954 7.129,46.954 7.829,46.954 19.924,47.005 12.85,47.057 0.817,47.4 17.322,47.391 25.826,47.498 14.526,47.553 11.36,47.669 19.147,47.783 12.723,47.959 16.544,48.168 18.369,48.561 16.118,48.666 96.786,48.667 11.36,48.769 12.677,48.946 14.223,48.946 15.766,48.946 17.591,49.339 11.36,49.869 12.677,50.046 14.223,50.046 15.766,50.046 17.512,50.508 11.36,50.969 12.677,51.146 14.223,51.146 15.766,51.146 17.512,51.556 11.36,52.069 12.677,52.246 17.912,52.375 11.36,53.169 12.677,53.346 16.539,53.44 18.616,53.44 51.592,53.85 19.393,53.873 20.493,53.873 21.593,53.873 22.693,53.873 23.793,53.873 24.893,53.873 25.993,53.873 27.093,53.873 28.193,53.873 29.293,53.873 30.393,53.873 31.493,53.873 32.593,53.873 33.693,53.873 34.793,53.873 35.893,53.873 36.993,53.873 38.093,53.873 39.193,53.873 40.293,53.873 41.393,53.873 42.493,53.873 43.593,53.873 44.693,53.873 45.793,53.873 46.893,53.873 47.993,53.873 49.093,53.873 50.193,53.873 52.815,53.972 14.8,54.029 17.317,54.218 11.36,54.269 12.74,54.269 53.593,54.75 15.578,54.807 18.095,54.996 11.35,55.058 13.563,55.129 54.371,55.528 16.356,55.585 20.55,55.75 21.65,55.75 22.75,55.75 23.85,55.75 24.95,55.75 26.05,55.75 27.15,55.75 28.25,55.75 29.35,55.75 30.45,55.75 31.55,55.75 32.65,55.75 33.75,55.75 34.85,55.75 35.95,55.75 37.05,55.75 38.15,55.75 39.25,55.75 40.35,55.75 41.45,55.75 42.55,55.75 43.65,55.75 44.75,55.75 45.85,55.75 46.95,55.75 48.05,55.75 49.15,55.75 50.25,55.75 51.35,55.75 18.873,55.774 11.928,55.836 14.341,55.907 52.248,56.134 55.149,56.306 17.134,56.362 12.706,56.614 15.119,56.685 53.026,56.911 55.927,57.084 17.912,57.14 98.79,57.3 13.483,57.392 15.896,57.463 53.804,57.689 56.704,57.861 18.689,57.918 78.357,58.019 20.55,58.05 21.65,58.05 22.75,58.05 23.85,58.05 24.95,58.05 26.05,58.05 27.15,58.05 28.25,58.05 29.35,58.05 30.45,58.05 31.55,58.05 32.65,58.05 33.75,58.05 34.85,58.05 35.95,58.05 37.05,58.05 38.15,58.05 39.25,58.05 40.35,58.05 41.45,58.05 42.55,58.05 43.65,58.05 44.75,58.05 45.85,58.05 46.95,58.05 48.05,58.05 49.15,58.05 50.25,58.05 51.35,58.05 14.261,58.17 16.674,58.24 19.596,58.25 54.582,58.467 52.14,58.502 57.482,58.639 17.452,59.018 55.36,59.245 52.918,59.28 18.23,59.796 56.137,60.023 53.696,60.058 20.55,60.15 21.65,60.15 22.75,60.15 23.85,60.15 24.95,60.15 26.05,60.15 27.15,60.15 28.25,60.15 29.35,60.15 30.45,60.15 32.65,60.15 33.75,60.15 34.85,60.15 35.95,60.15 37.05,60.15 38.15,60.15 39.25,60.15 40.35,60.15 41.45,60.15 42.55,60.15 43.65,60.15 44.75,60.15 45.85,60.15 46.95,60.15 48.05,60.15 49.15,60.15 50.25,60.15 51.35,60.15 31.557,60.467 16.595,60.503 56.915,60.8 54.473,60.836 51.856,61.048 6.366,61.193 7.909,61.193 17.372,61.281 57.693,61.578 55.251,61.614 52.634,61.825 18.15,62.059 31.557,62.365 58.471,62.356 56.029,62.392 20.55,62.598 21.65,62.598 22.75,62.598 23.85,62.598 24.95,62.598 26.05,62.598 27.15,62.598 28.25,62.598 29.35,62.598 30.45,62.598 32.65,62.598 33.75,62.598 34.85,62.598 35.95,62.598 37.05,62.598 38.15,62.598 39.25,62.598 40.35,62.598 41.45,62.598 42.55,62.598 43.65,62.598 44.525,62.598 45.625,62.598 53.412,62.603 46.733,62.636 47.833,62.636 48.933,62.636 50.033,62.636 59.249,63.134 56.807,63.169 54.189,63.381 51.485,63.475 60.026,63.912 57.585,63.947 61.996,63.947 54.967,64.159 52.262,64.253 60.505,64.565 58.363,64.725 55.745,64.937 53.04,65.031 61.996,65.047 58.983,65.394 60.505,65.665 56.523,65.715 53.818,65.809 61.996,66.147 57.301,66.492 58.983,66.494 54.596,66.586 60.505,66.765 61.996,67.247 55.374,67.364 57.301,67.592 58.983,67.594 60.505,67.865 55.665,68.169 61.996,68.347 57.301,68.692 58.983,68.694 60.505,68.965 55.665,69.269 61.996,69.447 57.301,69.792 58.983,69.794 60.505,70.065 55.665,70.369 61.996,70.547 57.301,70.892 58.983,70.894 60.505,71.165 55.665,71.469 61.996,71.647 57.301,71.992 58.983,71.994 60.505,72.265 55.665,72.569 61.996,72.747 57.301,73.092 58.983,73.094 45.325,73.165 60.505,73.365 55.665,73.669 61.996,73.847 87.482,73.836 57.301,74.192 58.983,74.194 60.505,74.465 55.665,74.769 61.996,74.947 57.301,75.292 58.983,75.294 87.482,75.536 60.505,75.565 55.665,75.869 61.996,76.047 57.301,76.392 58.983,76.394 60.505,76.665 55.665,76.969 61.996,77.147 82.3,77.2 57.301,77.492 58.983,77.494 60.505,77.765 85.184,77.842 55.665,78.069 61.996,78.247 57.301,78.592 58.983,78.594 60.505,78.865 55.665,79.169 61.996,79.347 57.301,79.692 58.983,79.694 60.505,79.965 55.665,80.269 62.213,80.493 57.301,80.792 58.983,80.794 60.505,81.065 62.991,81.271 55.665,81.369 61.081,81.84 57.301,81.892 58.983,81.894 63.769,82.048 91.2,82.4 55.665,82.469 59.546,82.627 61.859,82.618 54.887,82.791 64.547,82.826 57.301,82.992 62.637,83.396 60.324,83.405 55.665,83.569 65.324,83.604 58.078,83.77 61.102,84.183 63.415,84.173 56.443,84.347 66.102,84.382 58.856,84.548 61.88,84.961 64.192,84.951 57.221,85.124 66.88,85.16 59.634,85.326 64.97,85.729 62.658,85.739 57.998,85.902 67.658,85.937 60.412,86.104 63.435,86.516 65.748,86.507 58.776,86.68 68.436,86.715 61.19,86.881 66.526,87.285 64.213,87.294 59.554,87.458 23.25,87.5 69.213,87.493 61.968,87.659 64.991,88.072 67.304,88.063 23.25,88.1 60.332,88.236 69.991,88.271 62.745,88.437 23.25,88.7 65.769,88.85 68.081,88.84 61.11,89.014 70.769,89.049 63.523,89.215 72.032,89.236 73.732,89.236 68.859,89.618 66.547,89.628 61.887,89.791 71.547,89.826 23.25,90 64.301,89.993 67.324,90.405 69.637,90.396 62.665,90.569 23.25,90.6 72.642,90.62 65.079,90.77 68.102,91.183 70.415,91.174 23.25,91.2 63.443,91.347 65.857,91.548 68.88,91.961 64.221,92.125 66.634,92.326 23.25,92.5 69.658,92.739 70.61,92.783 71.71,92.783 64.999,92.903 23.25,93.1 67.412,93.104 65.776,93.68 23.25,93.7 68.19,93.882 69.616,93.988 70.716,93.988 71.896,94.019 72.996,94.019 66.554,94.458 23.25,95 67.332,95.236 68.432,95.236 69.532,95.236 70.632,95.236 71.732,95.236 72.832,95.236 73.932,95.236 23.25,95.6 92.289,95.868 23.25,96.2 81.759,97.518 92.328,98.528 86.9,103.25 23.573,103.603 84.233,104.448 85.179,104.444 81.248,113.8 81.248,115.8 77.169,126.978 37.932,133.636 39.432,133.636 40.332,133.636 41.832,133.636 85.53,134.12 85.88,134.12 86.23,134.12 36.732,134.836 38.232,134.836 39.132,134.836 40.632,134.836 86.88,135.15 87.23,135.15 87.58,135.15 87.93,135.15 89.23,135.15 89.58,135.15 89.93,135.15 90.28,135.15 84.88,135.45 85.23,135.45 85.58,135.45 86.88,135.45 87.23,135.45 87.93,135.45 89.23,135.45 89.93,135.45 90.28,135.45 82.91,135.6 82.36,135.75 82.21,136.3 82.36,136.85 82.91,137 81.99,137.75 82.39,137.75 82.79,137.75 81.99,138.25 82.39,138.25 82.79,138.25 39.832,138.336 41.332,138.336 81.99,138.75 82.39,138.75 82.79,138.75 35.5,138.8 81.99,139.25 82.39,139.25 82.79,139.25 84.45,139.5 81.99,139.75 82.39,139.75 82.79,139.75 34.8,140.2 44.866,140.69 45.927,141.751 87.18,141.958 85.255,141.995 81,142.047 83.23,142.07 52.259,142.14 52.959,142.14 68.43,142.504 60.05,142.515 66.804,142.84 70.648,143.092 34.9,143.2 69.572,143.21 55.804,143.34 56.504,143.34 58.873,143.359 58.304,143.64 20.625,143.891 74.74,144.117 30.7,144.6 56.446,144.859 69.143,144.897 64.648,144.95 16.925,144.991 63.716,145.04 21.794,145.06 67.443,145.197 72.393,145.206 42.995,145.282 73.908,145.58 54.741,145.783 53.158,145.797 70.747,145.858 50.297,145.969 32.1,146.1 18.094,146.16 53.13,146.526 65.413,146.608 43.023,146.643 51.538,146.738 42.409,147.011 41.403,147.193 66.312,147.201 64.143,147.482 13.126,147.852 14.779,147.852 62.506,147.89 44.398,148.032 64.121,148.036 48.855,148.201 40.985,148.228 26.5,148.3 64.035,148.679 48.215,148.775 41.926,149.131 45.938,149.258 47.363,149.261 48.215,149.471 62.889,149.526 61.611,149.544 78.463,150.113 62.884,150.343 13.048,150.45 16.048,150.45 17.701,150.45 75.1,150.6 76.649,150.6 14.701,150.65 73.628,150.651 72,150.7 78.768,151.474 62.567,152.133 60.979,152.493 53.782,152.752 56.825,152.765 60.979,153.14 27.959,153.366 33.911,154.056 30.4,154.465 32.1,154.465 36.728,154.977 38.8,155.365 40.5,155.365 36.659,156.584 45.689,156.765 47.289,156.765 46.139,157.215 46.839,157.215
  other v5: 10.6,0.8 10.6,2.452 14.117,2.549 10.6,3.102 10.6,3.702 10.6,4.402 65.03,4.709 56.062,4.79 57.862,4.79 10.6,5.102 76.798,5.62 77.848,5.674 80.048,5.674 10.6,5.802 58.335,6.247 10.6,6.502 63.948,6.594 68.581,6.859 69.481,6.859 70.381,6.859 73.848,6.974 10.6,7.202 57.274,7.307 76.798,7.32 63.204,7.364 68.581,7.759 69.481,7.759 70.381,7.759 10.6,7.902 73.748,8.074 63.948,8.106 10.6,8.602 68.581,8.659 69.481,8.659 70.381,8.659 73.748,9.074 10.6,9.302 10.6,10.002 10.6,10.702 10.6,11.402 11.3,12 11.9,12 10.6,12.102 12.367,12.413 12.293,13.052 71.048,13.174 10.6,13.2 73.1,13.225 11.762,13.3 10.6,13.8 11.901,13.801 12.397,14.327 10.6,14.4 12.1,14.8 10.6,15.1 11.6,15.2 10.6,15.8 11.657,15.866 13.55,15.95 20.15,15.95 71.25,16.375 72.95,16.375 10.6,16.5 11.632,16.525 12.65,16.85 13.55,16.85 14.45,16.85 19.25,16.85 20.15,16.85 21.05,16.85 71.75,16.875 72.45,16.875 11.628,17.175 10.6,17.2 11.776,17.689 13.55,17.75 20.15,17.75 10.6,17.9 12.958,18.152 11.373,18.578 10.6,18.6 11.902,18.65 13.55,19.25 10.6,19.3 10.6,20 12.65,20.15 13.55,20.15 14.45,20.15 19.25,20.15 20.15,20.15 21.05,20.15 10.6,20.7 13.55,21.05 20.15,21.05 10.6,21.4 10.6,22.1 24,22.51 38.665,22.744 10.6,22.8 24,23.31 10.6,23.601 37.179,23.729 39.975,23.875 10.6,24.301 38.465,24.889 10.6,25.001 10.6,25.701 26,25.98 33.469,26 39.341,26.074 11.789,26.167 40.94,26.203 10.6,26.401 11.144,26.459 36.275,26.575 73.269,26.575 12.988,26.682 71.875,26.875 10.6,27.001 43.103,26.997 11.777,27.176 37.67,27.373 10.6,27.6 43.856,27.609 11.64,27.634 10.6,28.201 11.64,28.201 19.106,28.225 98.45,28.397 81.009,28.643 18.806,28.675 69.862,28.795 10.6,28.901 11.64,28.901 15.443,29.052 39.46,29.181 43.302,29.175 18.806,29.275 55.52,29.403 37.924,29.573 10.6,29.601 11.64,29.601 19.106,29.725 10.6,30.301 11.64,30.301 15.443,30.352 14.825,30.413 81.091,30.449 10.6,31.001 11.64,31.001 73.691,31.049 74.591,31.049 76.391,31.049 81.091,31.049 18.806,31.475 55.52,31.503 10.6,31.701 11.64,31.701 15.025,31.763 72.791,31.949 73.691,31.949 74.591,31.949 75.491,31.949 76.391,31.949 18.806,32.075 68.091,32.249 10.6,32.401 11.64,32.401 13.849,32.425 19.106,32.525 68.091,32.849 72.791,32.849 73.691,32.849 74.591,32.849 75.491,32.849 76.391,32.849 10.6,33.101 11.64,33.101 35.96,33.581 68.516,33.624 10.6,33.701 13.849,33.725 72.791,33.749 73.691,33.749 74.591,33.749 75.491,33.749 76.391,33.749 11.64,33.801 19.106,33.825 12.1,34.101 10.6,34.201 35.96,34.181 18.806,34.275 12.417,34.651 72.791,34.649 73.691,34.649 74.591,34.649 75.491,34.649 76.391,34.649 10.6,34.701 18.806,34.875 12.185,35.149 13.427,35.225 10.6,35.301 19.106,35.325 11.733,35.535 68.116,35.849 10.6,35.901 12.202,35.909 12.386,36.422 13.427,36.525 10.6,36.901 12.165,36.901 11.097,37.004 18.806,37.075 11.613,37.11 10.6,37.501 18.806,37.675 11.45,38.024 19.106,38.125 10.6,38.201 10.6,38.901 11.45,39.324 10.005,39.396 9.51,39.891 9.015,40.386 8.674,40.859 8.674,41.559 8.674,42.259 8.674,42.959 8.674,43.659 17.978,44.16 8.674,44.359 8.674,45.059 8.674,45.759 1.179,46.254 3.279,46.254 3.979,46.254 4.679,46.254 5.379,46.254 6.079,46.254 6.779,46.254 7.479,46.254 8.179,46.254 0.817,46.7 3.629,46.954 4.329,46.954 5.029,46.954 5.729,46.954 6.429,46.954 7.129,46.954 7.829,46.954 0.817,47.4 25.826,47.498 10.65,54.269 26.416,55.234 31.541,55.234 98.79,57.3 78.357,58.019 19.596,58.25 18.23,59.796 19.25,60.15 31.557,60.467 19.25,62.35 31.557,62.365 50.75,62.45 45.325,73.165 87.482,73.836 34.086,74.376 87.482,75.536 82.3,77.2 85.184,77.842 87.06,82.726 56.682,85.65 23.25,87.5 23.25,88.1 23.25,88.7 72.032,89.236 73.732,89.236 23.25,90 23.25,90.6 23.25,91.2 71.432,91.636 23.25,92.5 72.632,92.836 74.332,92.836 23.25,93.1 23.25,93.7 73.832,94.036 75.532,94.036 23.25,95 76.732,95.236 23.25,95.6 92.289,95.868 23.25,96.2 72.982,96.436 92.328,98.528 73.982,98.836 75.382,98.836 76.582,100.036 72.982,101.236 78.226,102.892 75.532,103.636 76.882,104.235 71.582,106.036 72.982,106.036 73.932,107.236 75.432,107.236 75.232,108.436 76.532,108.436 78.182,109.235 77.582,109.829 71.082,110.236 77.582,110.529 78.182,111.135 81.248,115.8 77.169,126.978 44.432,132.436 45.932,132.436 47.032,132.436 48.532,132.436 37.932,133.636 39.432,133.636 40.332,133.636 41.832,133.636 43.282,133.636 44.782,133.636 45.682,133.636 47.182,133.636 48.232,133.636 49.732,133.636 36.732,134.836 38.232,134.836 39.132,134.836 40.632,134.836 39.832,138.336 41.332,138.336 66.021,139.291 48.659,141.04 66.021,141.191 48.582,141.791 52.582,141.791 68.43,142.504 60.05,142.515 66.804,142.84 70.648,143.092 69.572,143.21 55.804,143.34 56.504,143.34 58.873,143.359 48.703,143.383 58.304,143.64 47.21,143.844 20.625,143.891 74.74,144.117 48.061,144.35 56.446,144.859 69.143,144.897 64.648,144.95 16.925,144.991 63.716,145.04 21.794,145.06 67.443,145.197 72.393,145.206 42.995,145.282 73.908,145.58 54.741,145.783 53.158,145.797 70.747,145.858 50.297,145.969 18.094,146.16 53.13,146.526 65.413,146.608 43.023,146.643 51.538,146.738 42.409,147.011 41.403,147.193 66.312,147.201 64.143,147.482 13.126,147.852 14.779,147.852 62.506,147.89 44.398,148.032 64.121,148.036 48.855,148.201 40.985,148.228 64.035,148.679 48.215,148.775 41.926,149.131 45.938,149.258 47.363,149.261 48.215,149.471 62.889,149.526 61.611,149.544 78.463,150.113 62.884,150.343 13.048,150.45 16.048,150.45 17.701,150.45 75.1,150.6 76.649,150.6 14.701,150.65 73.628,150.651 72,150.7 78.768,151.474 62.567,152.133 60.979,152.493 35.395,152.57 53.782,152.752 56.825,152.765 60.979,153.14 27.959,153.366 33.911,154.056 30.4,154.465 32.1,154.465 36.728,154.977 38.8,155.365 40.5,155.365 36.659,156.584 45.689,156.765 47.289,156.765 46.139,157.215 46.839,157.215
  other v6: 62.826,5.6 95.3,7.9 80.844,14.29 83.384,15.305 83.384,17.335 81.236,17.352 83.384,19.365 80.844,20.38 83.384,21.395 80.844,22.41 87.011,27.6 87.36,29.285 90.111,30.4 39.341,30.599 40.841,30.599 42.341,30.599 43.841,30.599 86.911,31.2 66.221,31.974 39.341,32.099 40.841,32.099 42.341,32.099 43.841,32.099 67.269,33.334 39.341,33.599 40.841,33.599 42.341,33.599 43.841,33.599 64.864,34.229 84.375,34.675 36.06,34.781 39.341,35.099 40.841,35.099 42.341,35.099 75.713,39.149 91.6,39.9 91.45,42.2 76.302,43.596 74.223,45.516 51.202,47.799 52.472,47.799 53.742,47.799 55.012,47.799 56.282,47.799 57.552,47.799 58.822,47.799 60.092,47.799 51.202,48.669 52.472,48.669 53.742,48.669 55.012,48.669 56.282,48.669 57.552,48.669 58.822,48.669 60.092,48.669 71.393,53.881 39.282,82.036 47.682,83.236 90.313,86.697 9.727,86.769 28.482,89.236 5.23,92.165 28.482,92.836 34.482,92.836 5.025,92.966 5.025,93.766 92.25,97.45 88.85,100.6 96.5,102.85 5.025,106.365 5.025,107.165 5.025,107.965 71.682,108.676 90.655,108.95 64.482,110.836 71.682,111.916 5.025,117.665 5.025,118.465 95.955,119.05 5.025,119.265 98.38,120.15 33.282,121.636 70.482,122.836 18.299,133.087 17,133.4 19.7,134.2 82.124,134.316 85.88,134.82 86.33,135.42 68.232,136.336 69.932,136.336 71.632,136.336 73.332,136.336 75.032,136.336 76.732,136.336 83.19,142.75 84.33,143.02 75.49,146.25 25.682,151.636
  other v7: 74.075,57.5 74.575,57.5 74.075,60.5 74.575,60.5
GPIO4_SWDIO_33: TP39.X U5.27 U33_5.16 | length 45.2
  L8 w0.104: v3(97.205,98.545) 97.495,98.255 97.495,93.384 v4(97.311,93.2)
  L8 w0.127: v3(85.302,94.034) 85.302,94.009 85.155,93.862 85.155,93.446 v3(87.476,91.126)
  BOTTOM_L10 w0.104: U33_5.16@84.253,95.645 84.253,95.1 84.662,94.691 84.827,94.691 85.05,94.468 85.05,94.286 v3(85.302,94.034) ; U5.27@87.753,90.747 87.705,90.795 87.476,90.795 v3(87.476,91.126) 87.476,91.783 88.235,92.542 88.235,94.809 88.625,95.199 88.625,96.169 88.21,96.584 88.21,99.09 87.9,99.4 87.9,100.958 88.279,101.337 91.998,101.337 94.791,98.545 v3(97.205,98.545)
  BOTTOM_L10 w0.15: TP39.X@92.2,84.52 93.028,85.348 93.028,88.04 94.053,89.065 94.053,91.198 94.876,92.021 95.921,92.021 96.4,92.5 96.4,92.9 96.7,93.2 v4(97.311,93.2)
  other v3: 97.311,93.2
  other v4: 87.476,91.126 85.302,94.034 97.205,98.545
GPIO5_SWCLK_33: TP38.X U5.28 U33_5.15 | length 41.6
  L8 w0.1: v4(85.138,95.015) 85.16,95.015 85.45,94.725 85.65,94.525 86.091,94.525 87.34,95.774 v3(88.944,95.774) ; v3(96.855,98.253) 96.855,98.245 97.268,97.832 97.268,93.856 v3(97.011,93.6)
  BOTTOM_L10 w0.1: U33_5.15@84.753,95.645 84.753,95.245 84.954,95.044 85.109,95.044 v4(85.138,95.015) ; U5.28@87.753,90.347 88.171,90.347 88.312,90.488 88.312,90.727 88.281,90.758 88.281,92.303 88.437,92.458 88.437,94.725 88.827,95.116 88.827,95.616 88.944,95.733 88.944,96.135 88.423,96.656 88.423,99.227 88.102,99.548 88.102,100.801 88.436,101.135 91.915,101.135 94.805,98.245 96.847,98.245 v3(96.855,98.253)
  BOTTOM_L10 w0.15: TP38.X@92.2,87.06 92.2,88.027 92.532,88.359 92.907,88.359 93.759,89.21 93.759,91.45 94.633,92.324 95.724,92.324 96.145,92.745 96.145,93.078 96.64,93.572 96.984,93.572 v3(97.011,93.6)
  other v3: 85.138,95.015
  other v4: 97.011,93.6 88.944,95.774 96.855,98.253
